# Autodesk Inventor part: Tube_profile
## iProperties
Shininess: 69.0
Length Units: 11269
Angle Units: 11279
Time Units: 11290
Mass Units: 11283
Length Display Precision: 3
Angle Display Precision: 2
Created: 2001-04
Part Number: Tube_profile
Material: Standard
Document SubType Name: Modellieren
Designer: dl
Density: 1 g/cm^3
Density: 0.0
Volumn: 0.0
Area: 0.0
PropertySet Name: Model Information
Control State: 0
Master: False
Checked Out: False
Author: dl
